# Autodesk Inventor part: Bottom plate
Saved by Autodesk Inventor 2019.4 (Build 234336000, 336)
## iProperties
Created: 2020-04
Part Number: Bottom plate
Material: Generic
Document SubType Name: Modeling
Designer: Administrator
Density: 1 g/cm^3
Appearance: Default
Title: Bottom plate v8
Author: Administrator
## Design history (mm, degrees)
feature "Body1"
body "Solid1"
